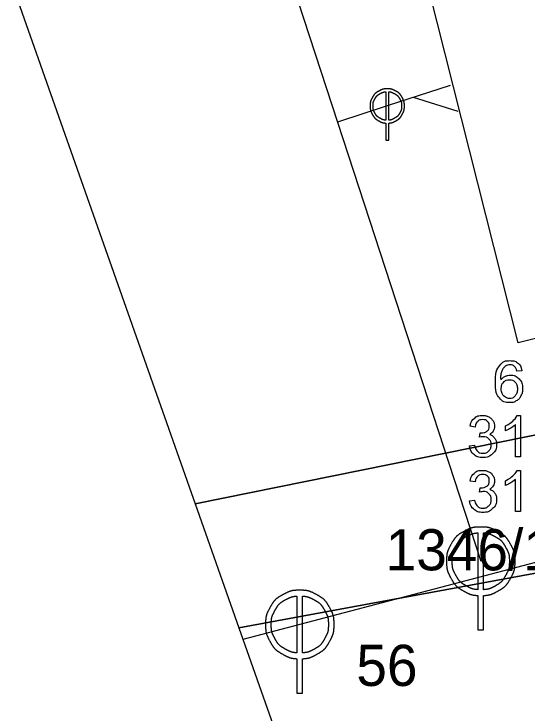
# Model space of a CAD drawing. Extents: x -562248 to -562040, y -1079385 to -1079027.
# Drawn here: x -562161.93 to -562143.23, y -1079149.79 to -1079124.27 of the extents above; entities that cross this region are included whole.
import ezdxf

# ---------------------------------------------------------------- set-up
doc = ezdxf.new("R2010")
doc.units = 0
for name, color, linetype in [('Default', 7, 'Continuous'), ('Kanalizační přípojka', 7, 'Continuous'), ('Kanalizační stoka', 7, 'Continuous'), ('Kanalizační šachta', 7, 'Continuous'), ('Parcela-polygon', 7, 'Continuous'), ('Parcela-text', 7, 'Continuous'), ('Popis šachty', 7, 'Continuous')]:
    doc.layers.add(name, color=color, linetype=linetype)

msp = doc.modelspace()

# ---------------------------------------------------------------- linework, layer by layer
at = {"layer": 'Default'}
for points in [[(-562148.32, -1079126.995), (-562148.426, -1079126.995), (-562148.528, -1079127.022), (-562148.628, -1079127.076)], [(-562148.012, -1079127.076), (-562148.112, -1079127.022), (-562148.214, -1079126.995), (-562148.32, -1079126.995)], [(-562148.628, -1079127.076), (-562148.727, -1079127.129), (-562148.805, -1079127.206), (-562148.861, -1079127.306)], [(-562148.77, -1079127.359), (-562148.724, -1079127.276), (-562148.659, -1079127.211), (-562148.576, -1079127.166)], [(-562148.576, -1079127.166), (-562148.505, -1079127.128), (-562148.436, -1079127.106), (-562148.371, -1079127.1)], [(-562148.269, -1079127.1), (-562148.202, -1079127.106), (-562148.134, -1079127.128), (-562148.064, -1079127.166)], [(-562148.064, -1079127.166), (-562147.981, -1079127.211), (-562147.916, -1079127.276), (-562147.868, -1079127.359)], [(-562147.779, -1079127.306), (-562147.835, -1079127.206), (-562147.913, -1079127.129), (-562148.012, -1079127.076)], [(-562148.861, -1079127.306), (-562148.917, -1079127.406), (-562148.945, -1079127.511), (-562148.945, -1079127.62)], [(-562148.84, -1079127.62), (-562148.84, -1079127.529), (-562148.817, -1079127.442), (-562148.77, -1079127.359)], [(-562147.868, -1079127.359), (-562147.821, -1079127.442), (-562147.798, -1079127.529), (-562147.798, -1079127.62)], [(-562147.695, -1079127.62), (-562147.695, -1079127.511), (-562147.723, -1079127.406), (-562147.779, -1079127.306)], [(-562148.945, -1079127.62), (-562148.945, -1079127.727), (-562148.917, -1079127.831), (-562148.862, -1079127.93)], [(-562148.772, -1079127.878), (-562148.817, -1079127.795), (-562148.84, -1079127.71), (-562148.84, -1079127.62)], [(-562147.798, -1079127.62), (-562147.798, -1079127.71), (-562147.82, -1079127.795), (-562147.866, -1079127.878)], [(-562147.777, -1079127.93), (-562147.722, -1079127.831), (-562147.695, -1079127.727), (-562147.695, -1079127.62)], [(-562148.862, -1079127.93), (-562148.807, -1079128.029), (-562148.729, -1079128.107), (-562148.63, -1079128.162)], [(-562148.579, -1079128.069), (-562148.662, -1079128.024), (-562148.726, -1079127.96), (-562148.772, -1079127.878)], [(-562147.866, -1079127.878), (-562147.911, -1079127.96), (-562147.976, -1079128.024), (-562148.059, -1079128.069)], [(-562148.008, -1079128.162), (-562147.908, -1079128.107), (-562147.831, -1079128.029), (-562147.777, -1079127.93)], [(-562148.63, -1079128.162), (-562148.544, -1079128.211), (-562148.458, -1079128.238), (-562148.371, -1079128.243)], [(-562148.371, -1079128.138), (-562148.44, -1079128.133), (-562148.509, -1079128.11), (-562148.579, -1079128.069)], [(-562148.059, -1079128.069), (-562148.13, -1079128.11), (-562148.2, -1079128.133), (-562148.269, -1079128.138)], [(-562148.269, -1079128.243), (-562148.182, -1079128.238), (-562148.095, -1079128.211), (-562148.008, -1079128.162)], [(-562144.91, -1079142.97), (-562145.122, -1079142.97), (-562145.327, -1079143.024), (-562145.525, -1079143.131)], [(-562144.296, -1079143.131), (-562144.495, -1079143.024), (-562144.7, -1079142.97), (-562144.91, -1079142.97)], [(-562145.525, -1079143.131), (-562145.724, -1079143.239), (-562145.879, -1079143.392), (-562145.992, -1079143.593)], [(-562145.813, -1079143.699), (-562145.721, -1079143.532), (-562145.591, -1079143.404), (-562145.425, -1079143.314)], [(-562145.425, -1079143.314), (-562145.282, -1079143.238), (-562145.144, -1079143.194), (-562145.013, -1079143.182)], [(-562144.807, -1079143.182), (-562144.676, -1079143.194), (-562144.539, -1079143.238), (-562144.397, -1079143.314)], [(-562144.397, -1079143.314), (-562144.231, -1079143.404), (-562144.101, -1079143.532), (-562144.008, -1079143.699)], [(-562143.828, -1079143.593), (-562143.941, -1079143.392), (-562144.097, -1079143.239), (-562144.296, -1079143.131)], [(-562145.992, -1079143.593), (-562146.104, -1079143.793), (-562146.16, -1079144.002), (-562146.16, -1079144.22)], [(-562145.952, -1079144.22), (-562145.952, -1079144.039), (-562145.906, -1079143.866), (-562145.813, -1079143.699)], [(-562144.008, -1079143.699), (-562143.914, -1079143.866), (-562143.868, -1079144.039), (-562143.868, -1079144.22)], [(-562143.66, -1079144.22), (-562143.66, -1079144.002), (-562143.716, -1079143.793), (-562143.828, -1079143.593)], [(-562146.16, -1079144.22), (-562146.16, -1079144.436), (-562146.105, -1079144.644), (-562145.995, -1079144.843)], [(-562145.816, -1079144.738), (-562145.907, -1079144.573), (-562145.952, -1079144.401), (-562145.952, -1079144.22)], [(-562143.868, -1079144.22), (-562143.868, -1079144.401), (-562143.913, -1079144.573), (-562144.004, -1079144.738)], [(-562143.825, -1079144.843), (-562143.715, -1079144.644), (-562143.66, -1079144.436), (-562143.66, -1079144.22)], [(-562145.995, -1079144.843), (-562145.885, -1079145.041), (-562145.731, -1079145.195), (-562145.533, -1079145.304)], [(-562145.43, -1079145.121), (-562145.596, -1079145.03), (-562145.725, -1079144.902), (-562145.816, -1079144.738)], [(-562144.004, -1079144.738), (-562144.095, -1079144.902), (-562144.223, -1079145.03), (-562144.388, -1079145.121)], [(-562144.287, -1079145.304), (-562144.089, -1079145.195), (-562143.935, -1079145.041), (-562143.825, -1079144.843)], [(-562145.013, -1079145.255), (-562145.149, -1079145.245), (-562145.288, -1079145.201), (-562145.43, -1079145.121)], [(-562144.388, -1079145.121), (-562144.531, -1079145.201), (-562144.671, -1079145.245), (-562144.807, -1079145.255)], [(-562151.509, -1079145.274), (-562151.721, -1079145.274), (-562151.926, -1079145.328), (-562152.124, -1079145.435)], [(-562150.895, -1079145.435), (-562151.094, -1079145.328), (-562151.299, -1079145.274), (-562151.509, -1079145.274)], [(-562145.533, -1079145.304), (-562145.358, -1079145.402), (-562145.185, -1079145.456), (-562145.013, -1079145.468)], [(-562144.807, -1079145.468), (-562144.635, -1079145.456), (-562144.462, -1079145.402), (-562144.287, -1079145.304)], [(-562152.124, -1079145.435), (-562152.323, -1079145.543), (-562152.478, -1079145.696), (-562152.591, -1079145.897)], [(-562152.412, -1079146.003), (-562152.32, -1079145.836), (-562152.19, -1079145.708), (-562152.024, -1079145.618)], [(-562152.024, -1079145.618), (-562151.881, -1079145.542), (-562151.743, -1079145.498), (-562151.612, -1079145.486)], [(-562151.406, -1079145.486), (-562151.275, -1079145.498), (-562151.138, -1079145.542), (-562150.996, -1079145.618)], [(-562150.996, -1079145.618), (-562150.83, -1079145.708), (-562150.7, -1079145.836), (-562150.607, -1079146.003)], [(-562150.427, -1079145.897), (-562150.54, -1079145.696), (-562150.696, -1079145.543), (-562150.895, -1079145.435)], [(-562152.591, -1079145.897), (-562152.703, -1079146.097), (-562152.759, -1079146.306), (-562152.759, -1079146.524)], [(-562152.551, -1079146.524), (-562152.551, -1079146.343), (-562152.505, -1079146.17), (-562152.412, -1079146.003)], [(-562150.607, -1079146.003), (-562150.513, -1079146.17), (-562150.467, -1079146.343), (-562150.467, -1079146.524)], [(-562150.259, -1079146.524), (-562150.259, -1079146.306), (-562150.315, -1079146.097), (-562150.427, -1079145.897)], [(-562152.759, -1079146.524), (-562152.759, -1079146.74), (-562152.704, -1079146.948), (-562152.594, -1079147.147)], [(-562152.415, -1079147.042), (-562152.506, -1079146.877), (-562152.551, -1079146.705), (-562152.551, -1079146.524)], [(-562150.467, -1079146.524), (-562150.467, -1079146.705), (-562150.512, -1079146.877), (-562150.603, -1079147.042)], [(-562150.424, -1079147.147), (-562150.314, -1079146.948), (-562150.259, -1079146.74), (-562150.259, -1079146.524)], [(-562152.594, -1079147.147), (-562152.484, -1079147.345), (-562152.33, -1079147.499), (-562152.132, -1079147.608)], [(-562152.029, -1079147.425), (-562152.195, -1079147.334), (-562152.324, -1079147.206), (-562152.415, -1079147.042)], [(-562150.603, -1079147.042), (-562150.694, -1079147.206), (-562150.822, -1079147.334), (-562150.987, -1079147.425)], [(-562150.886, -1079147.608), (-562150.688, -1079147.499), (-562150.534, -1079147.345), (-562150.424, -1079147.147)], [(-562152.132, -1079147.608), (-562151.957, -1079147.706), (-562151.784, -1079147.76), (-562151.612, -1079147.772)], [(-562151.612, -1079147.559), (-562151.748, -1079147.549), (-562151.887, -1079147.505), (-562152.029, -1079147.425)], [(-562150.987, -1079147.425), (-562151.13, -1079147.505), (-562151.27, -1079147.549), (-562151.406, -1079147.559)], [(-562151.406, -1079147.772), (-562151.234, -1079147.76), (-562151.061, -1079147.706), (-562150.886, -1079147.608)]]:
    msp.add_open_spline(points, degree=2, dxfattribs=at)
at = {"layer": 'Kanalizační přípojka'}
for points in [[(-562146.03, -1079126.87), (-562148.32, -1079127.62), (-562150.14, -1079128.21)], [(-562145.74, -1079127.82), (-562147.369, -1079127.31), (-562147.371, -1079127.309)]]:
    msp.add_lwpolyline(points, dxfattribs=at)
at = {"layer": 'Kanalizační stoka'}
for points in [[(-562156.26, -1079109.46), (-562155.056, -1079113.146), (-562150.14, -1079128.21), (-562144.91, -1079144.22)], [(-562123.19, -1079139.07), (-562151.509, -1079146.524)], [(-562151.509, -1079146.524), (-562153.584, -1079147.07)]]:
    msp.add_lwpolyline(points, dxfattribs=at)
at = {"layer": 'Kanalizační šachta'}
for points in [[(-562148.371, -1079127.1), (-562148.371, -1079128.138)], [(-562148.269, -1079128.138), (-562148.269, -1079127.1)], [(-562148.371, -1079128.87), (-562148.269, -1079128.87), (-562148.269, -1079128.243)], [(-562148.371, -1079128.243), (-562148.371, -1079128.87)], [(-562145.013, -1079143.182), (-562145.013, -1079145.255)], [(-562144.807, -1079145.255), (-562144.807, -1079143.182)], [(-562151.612, -1079145.486), (-562151.612, -1079147.559)], [(-562151.406, -1079147.559), (-562151.406, -1079145.486)], [(-562145.013, -1079146.72), (-562144.807, -1079146.72), (-562144.807, -1079145.468)], [(-562145.013, -1079145.468), (-562145.013, -1079146.72)], [(-562151.612, -1079149.024), (-562151.406, -1079149.024), (-562151.406, -1079147.772)], [(-562151.612, -1079147.772), (-562151.612, -1079149.024)]]:
    msp.add_lwpolyline(points, dxfattribs=at)
at = {"layer": 'Parcela-polygon'}
for p, q in [((-562155.326, -1079142.122), (-562153.733, -1079146.647)), ((-562153.733, -1079146.647), (-562151.942, -1079151.733))]:
    msp.add_line(p, q, dxfattribs=at)
for points in [[(-562132.29, -1079100.17), (-562132.68, -1079103.22), (-562132.95, -1079106.27), (-562133.02, -1079110.27), (-562133.03, -1079111.66), (-562133.02, -1079112.82), (-562132.9, -1079114.53), (-562132.89, -1079114.59), (-562132.42, -1079118.65), (-562131.55, -1079123.32), (-562130.11, -1079130.72), (-562129.93, -1079133.77), (-562130.82, -1079136.09), (-562133.17, -1079137.64), (-562132.36, -1079140.38), (-562140.21, -1079144.16), (-562153.733, -1079146.647)], [(-562156.09, -1079106.68), (-562161.93, -1079123.363), (-562155.326, -1079142.122)], [(-562155.326, -1079142.122), (-562133.17, -1079137.64), (-562134.27, -1079133.92), (-562143.55, -1079136.26), (-562147.68, -1079119.88), (-562138.41, -1079117.54), (-562138.9, -1079114.26), (-562147.01, -1079109.93), (-562156.09, -1079106.68)], [(-562153.733, -1079146.647), (-562140.21, -1079144.16), (-562132.36, -1079140.38), (-562133.17, -1079137.64), (-562155.326, -1079142.122)]]:
    msp.add_lwpolyline(points, dxfattribs=at)
msp.add_lwpolyline([(-562147.68, -1079119.88), (-562138.41, -1079117.54), (-562134.27, -1079133.92), (-562143.55, -1079136.26)], close=True, dxfattribs=at)
at = {"layer": 'Popis šachty'}
for points in [[(-562143.413, -1079137.279), (-562143.596, -1079137.293)], [(-562143.58, -1079138.905), (-562143.462, -1079138.905), (-562143.462, -1079140.41)], [(-562143.462, -1079140.41), (-562143.646, -1079140.41), (-562143.646, -1079139.237)], [(-562145.116, -1079139.327), (-562145.3, -1079139.293)], [(-562144.014, -1079139.459), (-562144.014, -1079139.281)], [(-562144.955, -1079139.699), (-562144.935, -1079139.538)], [(-562145.318, -1079140.013), (-562145.134, -1079139.989)], [(-562143.58, -1079140.905), (-562143.462, -1079140.905), (-562143.462, -1079142.41)], [(-562145.116, -1079141.327), (-562145.3, -1079141.293)], [(-562144.014, -1079141.459), (-562144.014, -1079141.281)], [(-562143.462, -1079142.41), (-562143.646, -1079142.41), (-562143.646, -1079141.237)], [(-562144.955, -1079141.699), (-562144.935, -1079141.538)], [(-562145.318, -1079142.013), (-562145.134, -1079141.989)]]:
    msp.add_lwpolyline(points, dxfattribs=at)
for points in [[(-562143.596, -1079137.293), (-562143.621, -1079137.184), (-562143.666, -1079137.135), (-562143.741, -1079137.056), (-562143.85, -1079137.056), (-562143.939, -1079137.056), (-562144.006, -1079137.105), (-562144.093, -1079137.168), (-562144.143, -1079137.29), (-562144.193, -1079137.412), (-562144.195, -1079137.637), (-562144.129, -1079137.536), (-562144.032, -1079137.487), (-562143.936, -1079137.437), (-562143.83, -1079137.437), (-562143.646, -1079137.437), (-562143.516, -1079137.573), (-562143.387, -1079137.708), (-562143.387, -1079137.923), (-562143.387, -1079138.064), (-562143.448, -1079138.186), (-562143.509, -1079138.307), (-562143.615, -1079138.371), (-562143.722, -1079138.436), (-562143.857, -1079138.436), (-562144.087, -1079138.436), (-562144.233, -1079138.266), (-562144.378, -1079138.097), (-562144.378, -1079137.708), (-562144.378, -1079137.274), (-562144.217, -1079137.076), (-562144.077, -1079136.905), (-562143.839, -1079136.905), (-562143.662, -1079136.905), (-562143.549, -1079137.004), (-562143.436, -1079137.103), (-562143.413, -1079137.279)], [(-562144.167, -1079137.924), (-562144.167, -1079138.019), (-562144.126, -1079138.107), (-562144.086, -1079138.194), (-562144.013, -1079138.239), (-562143.941, -1079138.285), (-562143.861, -1079138.285), (-562143.744, -1079138.285), (-562143.66, -1079138.19), (-562143.577, -1079138.096), (-562143.577, -1079137.935), (-562143.577, -1079137.779), (-562143.659, -1079137.689), (-562143.742, -1079137.6), (-562143.868, -1079137.6), (-562143.993, -1079137.6), (-562144.08, -1079137.689), (-562144.167, -1079137.779), (-562144.167, -1079137.924)], [(-562145.3, -1079139.293), (-562145.266, -1079139.108), (-562145.146, -1079139.006), (-562145.027, -1079138.905), (-562144.849, -1079138.905), (-562144.726, -1079138.905), (-562144.622, -1079138.957), (-562144.519, -1079139.01), (-562144.464, -1079139.101), (-562144.409, -1079139.192), (-562144.409, -1079139.294), (-562144.409, -1079139.391), (-562144.462, -1079139.471), (-562144.514, -1079139.55), (-562144.616, -1079139.597), (-562144.483, -1079139.628), (-562144.41, -1079139.725), (-562144.336, -1079139.821), (-562144.336, -1079139.966), (-562144.336, -1079140.163), (-562144.479, -1079140.299), (-562144.623, -1079140.436), (-562144.842, -1079140.436), (-562145.039, -1079140.436), (-562145.169, -1079140.318), (-562145.3, -1079140.2), (-562145.318, -1079140.013)], [(-562144.014, -1079139.281), (-562143.859, -1079139.208), (-562143.744, -1079139.105), (-562143.628, -1079139.002), (-562143.58, -1079138.905)], [(-562144.935, -1079139.538), (-562144.916, -1079139.54), (-562144.905, -1079139.54), (-562144.787, -1079139.54), (-562144.693, -1079139.479), (-562144.599, -1079139.417), (-562144.599, -1079139.29), (-562144.599, -1079139.188), (-562144.668, -1079139.122), (-562144.736, -1079139.056), (-562144.845, -1079139.056), (-562144.952, -1079139.056), (-562145.024, -1079139.123), (-562145.095, -1079139.191), (-562145.116, -1079139.327)], [(-562143.646, -1079139.237), (-562143.712, -1079139.301), (-562143.82, -1079139.364), (-562143.928, -1079139.427), (-562144.014, -1079139.459)], [(-562145.134, -1079139.989), (-562145.103, -1079140.145), (-562145.027, -1079140.214), (-562144.951, -1079140.283), (-562144.841, -1079140.283), (-562144.71, -1079140.283), (-562144.621, -1079140.193), (-562144.532, -1079140.103), (-562144.532, -1079139.97), (-562144.532, -1079139.844), (-562144.615, -1079139.761), (-562144.697, -1079139.679), (-562144.825, -1079139.679), (-562144.877, -1079139.679), (-562144.955, -1079139.699)], [(-562145.3, -1079141.293), (-562145.266, -1079141.108), (-562145.146, -1079141.006), (-562145.027, -1079140.905), (-562144.849, -1079140.905), (-562144.726, -1079140.905), (-562144.622, -1079140.957), (-562144.519, -1079141.01), (-562144.464, -1079141.101), (-562144.409, -1079141.192), (-562144.409, -1079141.294), (-562144.409, -1079141.391), (-562144.462, -1079141.471), (-562144.514, -1079141.55), (-562144.616, -1079141.597), (-562144.483, -1079141.628), (-562144.41, -1079141.725), (-562144.336, -1079141.821), (-562144.336, -1079141.966), (-562144.336, -1079142.163), (-562144.479, -1079142.299), (-562144.623, -1079142.436), (-562144.842, -1079142.436), (-562145.039, -1079142.436), (-562145.169, -1079142.318), (-562145.3, -1079142.2), (-562145.318, -1079142.013)], [(-562144.014, -1079141.281), (-562143.859, -1079141.208), (-562143.744, -1079141.105), (-562143.628, -1079141.002), (-562143.58, -1079140.905)], [(-562144.935, -1079141.538), (-562144.916, -1079141.54), (-562144.905, -1079141.54), (-562144.787, -1079141.54), (-562144.693, -1079141.479), (-562144.599, -1079141.417), (-562144.599, -1079141.29), (-562144.599, -1079141.188), (-562144.668, -1079141.122), (-562144.736, -1079141.056), (-562144.845, -1079141.056), (-562144.952, -1079141.056), (-562145.024, -1079141.123), (-562145.095, -1079141.191), (-562145.116, -1079141.327)], [(-562143.646, -1079141.237), (-562143.712, -1079141.301), (-562143.82, -1079141.364), (-562143.928, -1079141.427), (-562144.014, -1079141.459)], [(-562145.134, -1079141.989), (-562145.103, -1079142.145), (-562145.027, -1079142.214), (-562144.951, -1079142.283), (-562144.841, -1079142.283), (-562144.71, -1079142.283), (-562144.621, -1079142.193), (-562144.532, -1079142.103), (-562144.532, -1079141.97), (-562144.532, -1079141.844), (-562144.615, -1079141.761), (-562144.697, -1079141.679), (-562144.825, -1079141.679), (-562144.877, -1079141.679), (-562144.955, -1079141.699)]]:
    msp.add_open_spline(points, degree=3, dxfattribs=at)

# ---------------------------------------------------------------- texts
at = {"layer": 'Parcela-text'}
msp.add_text('1346/13', height=1.5, dxfattribs=at).set_placement((-562148.38, -1079144.55))
at = {"layer": 'Popis šachty'}
msp.add_text('56', height=1.5, dxfattribs=at).set_placement((-562149.448, -1079148.764))

doc.saveas('drawing.dxf')
